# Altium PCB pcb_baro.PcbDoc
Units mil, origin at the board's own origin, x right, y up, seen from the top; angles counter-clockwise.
Board outline 4060 x 1590 mil, 2 copper layers (Top Layer, Bottom Layer); 40 components, 31 nets, 117 pads, 4 vias.
Unrouted connection lines stored in the file: 2.
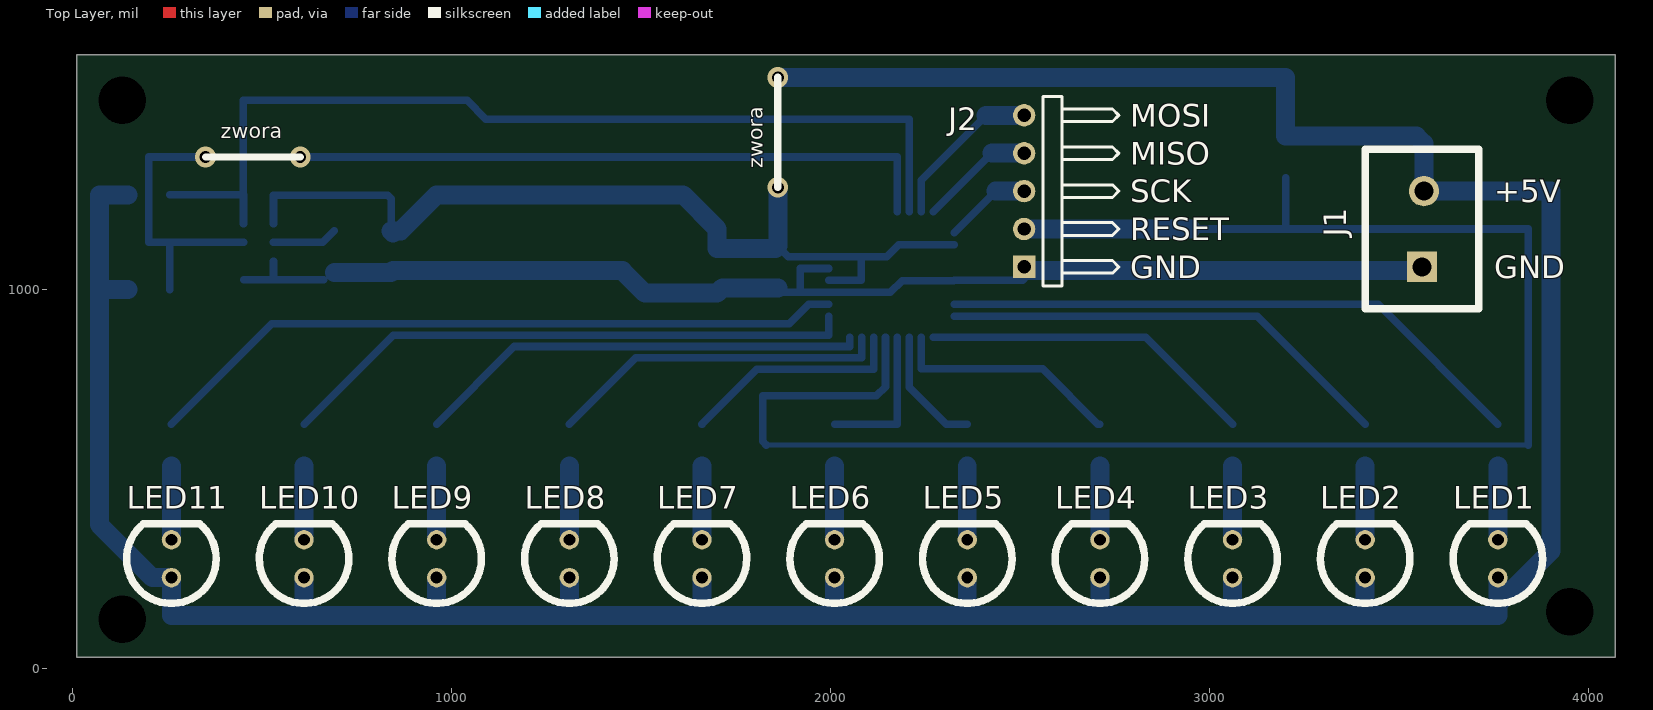
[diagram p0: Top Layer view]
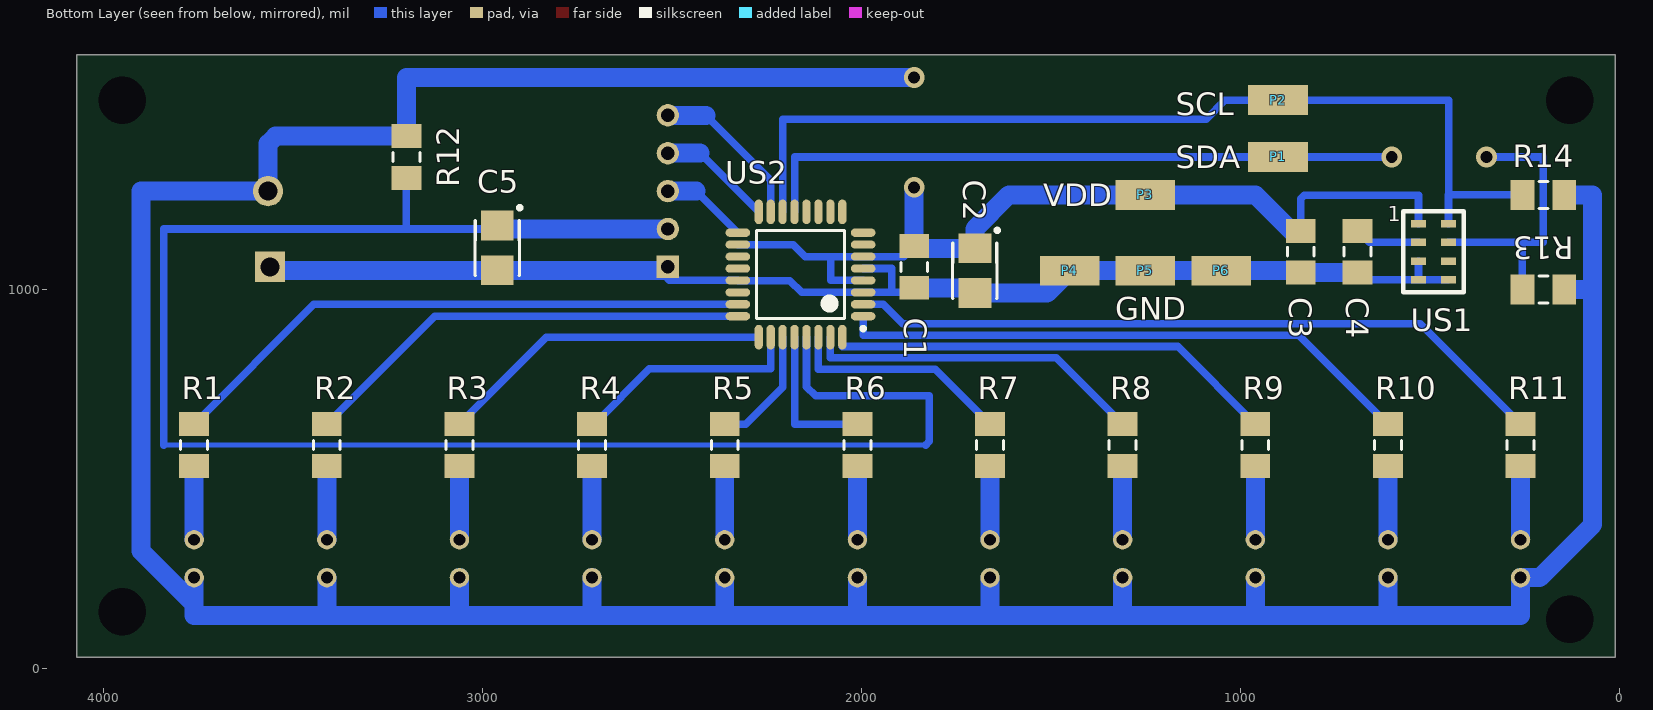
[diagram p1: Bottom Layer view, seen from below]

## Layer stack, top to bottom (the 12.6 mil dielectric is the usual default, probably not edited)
Top Layer: signal copper 1.4
Dielectric: dielectric 12.6, FR-4, Dk 4.8
Bottom Layer: signal copper 1.4

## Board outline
10,30 10,1620 4070,1620 4070,30

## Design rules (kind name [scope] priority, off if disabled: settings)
Clearance [All] p1: gap=10
PolygonConnect [All] p1: connectstyle=Relief reliefconductorwidth=10 reliefentries=4 polygonreliefangle="90 Angle"
RoutingVias [All] p1: holewidth=28 width=50 viastyle="Through Hole" minholewidth=28 minwidth=50 maxholewidth=28 maxwidth=50
SilkscreenOverComponentPads [All] p1: minsilkscreentomaskgap=10
SolderMaskExpansion [All] p1: expansion=4
Width [All] p1: maxlimit=100 minlimit=10 preferedwidth=50
27 further rules are at their usual default settings.

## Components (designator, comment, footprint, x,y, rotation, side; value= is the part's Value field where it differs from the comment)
C1 "100n" MELF-1206 1860,1060 r270 bottom
C2 "22u" "Tantal B 3528-1411" 1700,1050 r270 bottom
C3 "100n" MELF-1206 840,1100 r270 bottom
C4 "1u" MELF-1206 690,1100 r270 bottom
C5 "22u" "Tantal B 3528-1411" 2960,1110 r270 bottom
J1 "ARK2 5mm" "ARK2 5mm" 3560,1160 r90 top
J2 "Header 5H" HDR1X5H 2510,1060 r90 top
LED1 "LED" "LED 5mm" 3760,290 r270 top
LED2 "LED" "LED 5mm" 3410,290 r270 top
LED3 "LED" "LED 5mm" 3060,290 r270 top
LED4 "LED" "LED 5mm" 2710,290 r270 top
LED5 "LED" "LED 5mm" 2360,290 r270 top
LED6 "LED" "LED 5mm" 2010,290 r270 top
LED7 "LED" "LED 5mm" 1660,290 r270 top
LED8 "LED" "LED 5mm" 1310,290 r270 top
LED9 "LED" "LED 5mm" 960,290 r270 top
LED10 "LED" "LED 5mm" 610,290 r270 top
LED11 "LED" "LED 5mm" 260,290 r270 top
P1 "SDA" "Pad SMD 2x4mm" 900,1350 r180 bottom
P2 "SCL" "Pad SMD 2x4mm" 900,1500 r180 bottom
P3 "VDD" "Pad SMD 2x4mm" 1250,1250 r180 bottom
P4 "GND" "Pad SMD 2x4mm" 1450,1050 r180 bottom
P5 "GND" "Pad SMD 2x4mm" 1250,1050 r180 bottom
P6 "GND" "Pad SMD 2x4mm" 1050,1050 r180 bottom
R1 "750" MELF-1206 3760,590 r270 bottom
R2 "750" MELF-1206 3410,590 r270 bottom
R3 "750" MELF-1206 3060,590 r270 bottom
R4 "750" MELF-1206 2710,590 r270 bottom
R5 "750" MELF-1206 2360,590 r270 bottom
R6 "750" MELF-1206 2010,590 r270 bottom
R7 "750" MELF-1206 1660,590 r270 bottom
R8 "750" MELF-1206 1310,590 r270 bottom
R9 "750" MELF-1206 960,590 r270 bottom
R10 "750" MELF-1206 610,590 r270 bottom
R11 "750" MELF-1206 260,590 r270 bottom
R12 "4,7k" MELF-1206 3200,1350 r270 bottom
R13 "4,7k" MELF-1206 200,1000 r0 bottom
R14 "4,7k" MELF-1206 200,1250 r0 bottom
US1 "MPL115A2" MPL115A2 490,1100 r180 bottom
US2 "ATmega8-16AI" 32A_N 2160,1040 r0 bottom

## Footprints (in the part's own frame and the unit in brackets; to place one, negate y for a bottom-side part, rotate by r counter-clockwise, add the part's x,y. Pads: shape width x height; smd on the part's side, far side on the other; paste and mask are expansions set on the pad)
32A_N [mm] "Thin QFP, 32-Leads, Body 7x7mm, Pitch 0.8mm, IPC Medium Density"
  oval 1.65x0.55 smd: 1(-4.2,2.8) 2(-4.2,2) 3(-4.2,1.2) 4(-4.2,0.4) 5(-4.2,-0.4) 6(-4.2,-1.2) 7(-4.2,-2) 8(-4.2,-2.8) 17(4.2,-2.8) 18(4.2,-2) 19(4.2,-1.2) 20(4.2,-0.4) 21(4.2,0.4) 22(4.2,1.2) 23(4.2,2) 24(4.2,2.8)
  oval 0.55x1.65 smd: 9(-2.8,-4.2) 10(-2,-4.2) 11(-1.2,-4.2) 12(-0.4,-4.2) 13(0.4,-4.2) 14(1.2,-4.2) 15(2,-4.2) 16(2.8,-4.2) 25(2.8,4.2) 26(2,4.2) 27(1.2,4.2) 28(0.4,4.2) 29(-0.4,4.2) 30(-1.2,4.2) 31(-2,4.2) 32(-2.8,4.2)
  silkscreen extent -4.32,-2.95 2.95,3.75, body extent -3.5,-3.5 3.5,3.5, height 1.2
"ARK2 5mm" [mil]
  rect 80x80 hole 50: 1(-100,0)
  round 80 hole 50: 2(100,-5)
  silkscreen extent -210,-150 210,150, body extent -220,-160 220,160, height 394
HDR1X5H [mm] "Connector; Header; 5 Position; Right Angle"
  rect 1.5x1.5 hole 0.9: 1(0,0)
  round 1.5 hole 0.9: 2(2.54,0) 3(5.08,0) 4(7.62,0) 5(10.16,0)
  silkscreen extent -1.27,-6.35 11.43,-1.27
"LED 5mm" [mm]
  round 1.3 hole 0.8: A(1.27,0) K(-1.27,0)
  silkscreen extent -2.35,-3 3,3
MELF-1206 [mm] "Metal Electrode Face (MELF) Resistor; Body 3.2 x 1.8 mm (LxDia)"
  rect 1.6x2 smd: 1(-1.4,0) 2(1.4,0)
  silkscreen extent -0.3,-0.9 0.3,0.9, body extent -2.3,-1.1 2.3,1.1, height 1.85
MPL115A2 [mm]
  rect 1x0.5 smd: 1(-1,1.875) 2(-1,0.625) 3(-1,-0.625) 4(-1,-1.875) 5(1,-1.875) 6(1,-0.625) 7(1,0.625) 8(1,1.875)
  silkscreen extent -2.03,-2.7 2.03,2.7
"Pad SMD 2x4mm" [mm]
  rect 4x2 smd: 1(0,0)
"Tantal B 3528-1411" [mm] "Capacitor, SM Tantalum; Body 3.5 x 2.8 mm (LxW typ)"
  rect 2x2.2 smd: 1(-1.5,0) 2(1.5,0)
  silkscreen extent -2.82,-1.5 1.85,1.62, body extent -2.6,-1.2 2.6,1.2, height 2.5

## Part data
C1 C3 C4: library part kondensator
C2 C5: library part "kond biegunowy", "Polarized Capacitor"
J1: library part ARK2
J2: "Header, 5-Pin, Right Angle"
P1 P2 P3 P4 P5 P6: library part Pad, "Pad"
R1 R2 R3 R4 R5 R6 R7 R8 R9 R10 R11 R12 R13 R14: library part rezystor
US2: "8-Bit AVR Microcontroller with 8K Bytes of In-System Programmable Flash Memory"

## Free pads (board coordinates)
  rect 78.74x78.74 hole 125.98: 0(130,130) 1(3950,150) 2(3950,1500) 3(130,1500)

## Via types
v1: diameter 55.12, hole 31.5, Top Layer to Bottom Layer, 4 vias

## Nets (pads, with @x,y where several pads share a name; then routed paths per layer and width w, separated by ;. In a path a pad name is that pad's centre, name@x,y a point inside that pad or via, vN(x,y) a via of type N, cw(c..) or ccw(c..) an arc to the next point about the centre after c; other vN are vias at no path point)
GND: C1.2 C2.2 C3.2 C4.2 C5.2 J1.1 J2.1 P4.1 P5.1 P6.1 US1.3 US1.4 US1.5 US2.3 US2.5 US2.21 | length 3358.9
  Bottom Layer w20: US1.5 US1.4 ; US1.3 US1.4 ; C4.2@661.3,1026.18 US1.4 ; C1.2 1872.13,992.76 1919.76,992.76 ; US2.5 1919.76,1055.75 1919.76,992.76 ; J2.1@2519.06,1050.94 J2.1 2510,1028.5 2505.75,1024.25 US2.21 2324.68,1023.58 2188.07,1023.58 2157.24,992.76 US2.3 1919.76,992.76
  Bottom Layer w50: C4.2 C3.2 845.12,1050 P6.1 P5.1 P4.1 1509.06,990.94 C2.2 1713.94,1004.88 C1.2 ; J2.1@2519.06,1050.94 C5.2 3550.94,1050.94 J1.1
NetC4_1: C4.1 US1.2 | length 173.3
  Bottom Layer w20: US1.2 659.49,1124.61 C4.1
NetC5_1: C5.1 J2.2 R12.2 US2.29 | length 4638.4
  Bottom Layer w12: 1830,590 3840,590 ; C5.1 C5.1@2969.06,1160
  Bottom Layer w20: 1830,590 1820,600 1820,720 2120,720 2144.25,744.25 US2.29 ; C5.1@2969.06,1160 3200,1160 ; R12.2 3200,1160 ; 3840,590 3840,1160 3200,1160
  Bottom Layer w50: J2.2 C5.1@2950.94,1160
NetJ2_3: J2.3 US2.17 | length 230.1
  Bottom Layer w20: US2.17 2435.12,1260
  Bottom Layer w50: 2435.12,1260 J2.3
NetJ2_4: J2.4 US2.16 | length 303.8
  Bottom Layer w20: US2.16 2424.88,1360
  Bottom Layer w50: 2424.88,1360 J2.4
NetJ2_5: J2.5 US2.15 | length 425.6
  Bottom Layer w20: US2.15 2238.74,1288.74 2410,1460
  Bottom Layer w50: 2410,1460 J2.5
NetLED1_K: LED1.K R1.2 | length 194.9
  Bottom Layer w50: LED1.K R1.2
NetLED2_K: LED2.K R2.2 | length 194.9
  Bottom Layer w50: LED2.K R2.2
NetLED3_K: LED3.K R3.2 | length 194.9
  Bottom Layer w50: LED3.K R3.2
NetLED4_K: LED4.K R4.2 | length 194.9
  Bottom Layer w50: LED4.K R4.2
NetLED5_K: LED5.K R5.2 | length 194.9
  Bottom Layer w50: LED5.K R5.2
NetLED6_K: LED6.K R6.2 | length 194.9
  Bottom Layer w50: LED6.K R6.2
NetLED7_K: LED7.K R7.2 | length 194.9
  Bottom Layer w50: LED7.K R7.2
NetLED8_K: LED8.K R8.2 | length 194.9
  Bottom Layer w50: LED8.K R8.2
NetLED9_K: LED9.K R9.2 | length 194.9
  Bottom Layer w50: LED9.K R9.2
NetLED10_K: LED10.K R10.2 | length 194.9
  Bottom Layer w50: LED10.K R10.2
NetLED11_K: LED11.K R11.2 | length 194.9
  Bottom Layer w50: LED11.K R11.2
NetP1_1: P1.1 R13.2 US1.7 US2.13 | length 2590.5
  Bottom Layer w20: R13.2 255.12,1124.61 US1.7 ; v1(350,1350) 200,1350 200,1124.61 374.61,1124.61 ; v1(600,1350) P1.1 2175.75,1350 US2.13
NetP2_1: P2.1 R14.2 US1.8 US2.14 | length 2619.8
  Bottom Layer w20: R14.2 450.63,1250 US1.8 ; US1.8@450,1174.45 450,1500 1040,1500 1090,1450 2207.24,1450 US2.14
NetR1_1: R1.1 US2.23 | length 1565.6
  Bottom Layer w20: US2.23 3443.86,961.26 R1.1
NetR2_1: R2.1 US2.24 | length 1202.5
  Bottom Layer w20: US2.24 3125.35,929.76 R2.1
NetR3_1: R3.1 US2.25 | length 884.8
  Bottom Layer w20: US2.25 2830.47,874.65 R3.1
NetR4_1: R4.1 US2.26 | length 615.2
  Bottom Layer w20: US2.26 2238.74,791.26 2410,791.26 2558.74,791.26 2704.88,645.12 R4.1
NetR5_1: R5.1 US2.27 | length 325.1
  Bottom Layer w20: US2.27 2207.24,742.76 2304.88,645.12 R5.1
NetR6_1: R6.1 US2.28 | length 395.3
  Bottom Layer w20: R6.1 2076.61,645.12 2175.75,645.12 2175.75,744.25 US2.28
NetR7_1: R7.1 US2.30 | length 597.4
  Bottom Layer w20: R7.1 1804.88,790 2112.76,790 US2.30
NetR8_1: R8.1 US2.31 | length 898.3
  Bottom Layer w20: R8.1 1484.88,820 2081.26,820 US2.31
NetR9_1: R9.1 US2.32 | length 1199.3
  Bottom Layer w20: R9.1 1164.88,850 2049.76,850 US2.32
NetR10_1: R10.1 US2.1 | length 1531.7
  Bottom Layer w20: R10.1 844.88,880 1994.65,880 US2.1
NetR11_1: R11.1 US2.2 | length 1865.6
  Bottom Layer w20: R11.1 524.88,910 1890,910 1941.26,961.26 US2.2
VCC: C1.1 C2.1 C3.1 J1.2 LED1.A LED2.A LED3.A LED4.A LED5.A LED6.A LED7.A LED8.A LED9.A LED10.A LED11.A P3.1 R12.1 R13.1 R14.1 US1.1 US2.4 US2.6 US2.18 | length 11759.4
  Bottom Layer w20: US1.1 529.37,1249.37 830.63,1249.37 840,1240 C3.1 ; C1.1 1887.87,1087.24 US2.6 2080,1087.24 ; US2.4 2080,1024.25 2080,1087.24 ; US2.18 2178.74,1118.74 2147.24,1087.24 2080,1087.24
  Bottom Layer w50: 80,1000 R13.1 ; R14.1 70,1250 70,380 210,240 LED11.A 260,140 610,140 ; LED10.A 610,140 ; C3.1@845.12,1150 C3.1 865.12,1155.12 960,1250 1610,1250 1700,1160 C2.1 1853.94,1109.06 C1.1 v1(1860,1270) ; LED9.A 960,140 ; LED8.A 1310,140 ; LED7.A 1660,140 ; v1(1860,1560) 3200,1560 R12.1 3544.88,1405.12 3565,1385 J1.2 3900,1260 3900,310 3760,170 ; LED6.A 2010,140 ; LED5.A 2360,140 ; LED4.A 2710,140 ; LED3.A 3060,140 ; LED2.A 3410,140 ; LED1.A 3760,170 ; 610,140 960,140 ; 960,140 1310,140 ; 1310,140 1660,140 ; 1660,140 2010,140 ; 2010,140 2360,140 ; 2360,140 2710,140 ; 2710,140 3060,140 ; 3060,140 3410,140 ; 3410,140 3760,140 3760,170
pads on no net: US1.6 US2.7 US2.8 US2.9 US2.10 US2.11 US2.12 US2.19 US2.20 US2.22

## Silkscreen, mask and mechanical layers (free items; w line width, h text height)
Top Overlay:
  lines w19.68: 350,1350 600,1350 ; 1860,1270 1860,1560
  text "MOSI" at 2790,1430 h60
  text "zwora" at 390,1400 h39.37
  text "MISO" at 2790,1330 h60
  text "zwora" at 1820,1320 h39.37 r90
  text "SCK" at 2790,1230 h60
  text "+5V" at 3750,1230 h60
  text "RESET" at 2790,1130 h60
  text "GND" at 2790,1030 h60
  text "GND" at 3750,1030 h60
Mechanical 1:
  the board outline again, w10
